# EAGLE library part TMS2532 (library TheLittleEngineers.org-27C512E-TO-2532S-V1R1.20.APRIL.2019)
TMS2532 Copyright ©07 Jan 2013, by: Robert "The R.A.T." Allen Turner http://www.TheLittleEngineers.org/ TheLittleEngineers@outlook.com OurLittleEngineers@gMail.com You may use these components in your own projects, however, please take note that we CANNOT guarantee the accuracy of these components (nor any part of this library). We make NO guarantees that the components, footprints or schematic symbols in this library are flawless, and we make no promises of fitness for production, prototyping or any other purpose. These libraries are provided for informational purposes only, and are used at your own discretion. By downloading these libraries, you agree that we cannot be held responsible for faulty PCBs. You should always check the footprints with a 1:1 printout. Neither Robert Allen Turner, The Little Engineers, TheLittleEngineers.org, GIMEchip.com, nor anyone affiliated with same shall be held responsible for any outcome resulting from the usage of these files. Should any errors be found, please contact us at one of the above email addresses and we will attempt to repair them. Unless otherwise noted, content of this library is licensed under a Creative Commons Attribution-ShareAlike 4.0 International (CC BY-SA 4.0) license (https://creativecommons.org/licenses/by-sa/4.0/) on 20 April 2019 in memory of my Father, Robert Embry Turner - I LOVE YOU DAD! Rest In Peace. Please note that the GIMEchip.com domain was acquired by Robert "The R.A.T." Allen Turner on December 24, 2018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
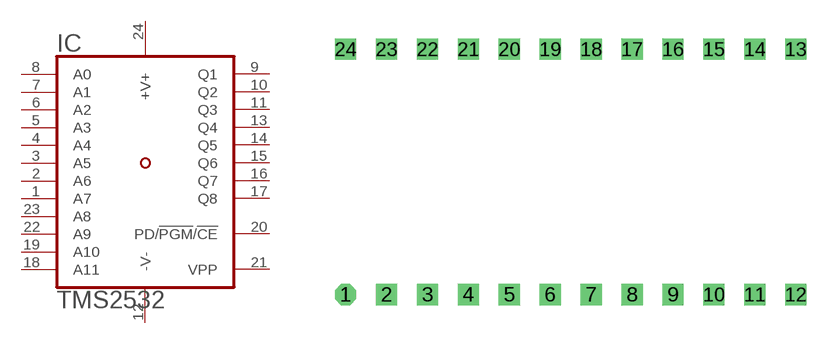
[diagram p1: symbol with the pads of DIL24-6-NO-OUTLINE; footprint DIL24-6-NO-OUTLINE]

Designator prefix IC

## TMS2532-NO  [DIL24-6-NO-OUTLINE]
1  A7  in
2  A6  in
3  A5  in
4  A4  in
5  A3  in
6  A2  in
7  A1  in
8  A0  in
9  Q1  hiz
10  Q2  hiz
11  Q3  hiz
12  -V-  pwr
13  Q4  hiz
14  Q5  hiz
15  Q6  hiz
16  Q7  hiz
17  Q8  hiz
18  A11  in
19  A10  in
20  PD/!PGM!/!CE  in
21  VPP  in
22  A9  in
23  A8  in
24  +V+  pwr

## Footprint DIL24-6-NO-OUTLINE (pad centres in mm)
Dual In Line Package (DIP) Socket Row Spacing: 0.6 inch (15.24 mm/600 mil) Number of Pins: (Grid): 24 (2 x 12) Pitch: 0.100 inch (2.54mm) Mounting Type: Through Hole Copyright ©07 Jan 2013, by: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
drill 0.813 octagon: 1 -13.97,-7.62
drill 0.813 square: 2 -11.43,-7.62; 3 -8.89,-7.62; 4 -6.35,-7.62; 5 -3.81,-7.62; 6 -1.27,-7.62; 7 1.27,-7.62; 8 3.81,-7.62; 9 6.35,-7.62; 10 8.89,-7.62; 11 11.43,-7.62; 12 13.97,-7.62; 13 13.97,7.62; 14 11.43,7.62; 15 8.89,7.62; 16 6.35,7.62; 17 3.81,7.62; 18 1.27,7.62; 19 -1.27,7.62; 20 -3.81,7.62; 21 -6.35,7.62; 22 -8.89,7.62; 23 -11.43,7.62; 24 -13.97,7.62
